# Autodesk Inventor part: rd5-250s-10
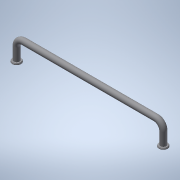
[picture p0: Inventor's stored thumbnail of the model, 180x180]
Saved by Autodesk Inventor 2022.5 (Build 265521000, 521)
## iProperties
Created: 2016-12
Part Number: rd5-250s-10
Material: 一般
Document SubType Name: Modeling
Designer: imaocorp
Density: 1 g/cm^3
Appearance: 既定
Author: imaocorp
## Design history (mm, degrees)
node "rd5-250s-10.x_t1"
node "rd5-250s-10"
node "Base1"
